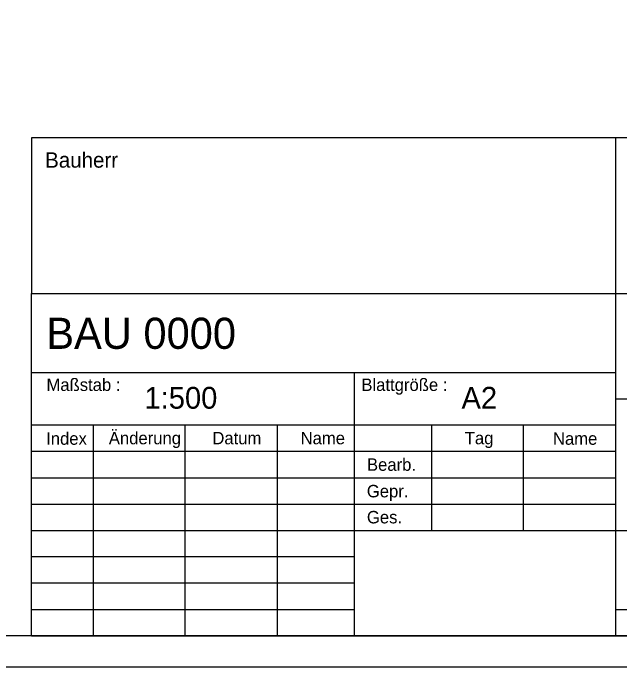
# Model space of a CAD drawing. Extents: x 0 to 297, y 0 to 210.
# Drawn here: x 204.1 to 252.8, y 0 to 52.5 of the extents above; entities that cross this region are included whole.
import ezdxf

# ---------------------------------------------------------------- set-up
doc = ezdxf.new("R2010")
doc.units = 0
doc.layers.add('90_Plankopf', color=7, linetype='Continuous')

msp = doc.modelspace()

# ---------------------------------------------------------------- linework, layer by layer
at = {"layer": '90_Plankopf'}
for p, q in [((294.5, 42.495), (205.56, 42.495)), ((205.56, 42.495), (205.56, 29.995)), ((252.501, 29.995), (252.501, 42.495)), ((205.56, 29.995), (294.5, 29.995)), ((205.56, 2.5), (205.56, 29.995)), ((205.56, 29.995), (294.5, 29.995)), ((252.501, 2.5), (252.501, 29.995)), ((205.56, 23.65), (252.501, 23.65)), ((231.501, 2.5), (231.501, 23.65)), ((252.501, 21.535), (294.5, 21.535)), ((205.56, 19.435), (252.501, 19.435)), ((210.501, 19.42), (210.501, 2.5)), ((217.913, 2.5), (217.913, 19.42)), ((225.325, 2.5), (225.325, 19.42)), ((237.677, 19.42), (237.677, 10.96)), ((245.089, 10.96), (245.089, 19.42)), ((205.56, 17.315), (252.501, 17.315)), ((205.56, 15.19), (252.501, 15.19)), ((205.56, 13.075), (252.501, 13.075)), ((205.56, 10.96), (252.501, 10.96)), ((205.56, 10.96), (252.501, 10.96)), ((231.501, 10.96), (252.501, 10.96)), ((252.501, 10.96), (294.5, 10.96)), ((231.501, 8.845), (205.56, 8.845)), ((231.501, 6.73), (205.56, 6.73)), ((205.56, 4.615), (231.501, 4.615)), ((252.501, 4.615), (294.5, 4.615)), ((294.5, 2.5), (205.56, 2.5)), ((205.56, 2.5), (231.501, 2.5)), ((211.4, 2.5), (294.5, 2.5)), ((211.4, 2.5), (294.5, 2.5))]:
    msp.add_line(p, q, dxfattribs=at)
for points in [[(0, 0), (297, 0), (297, 210), (0, 210)], [(12.5, 207.5), (294.5, 207.5), (294.5, 2.5), (12.5, 2.5)]]:
    msp.add_lwpolyline(points, close=True, dxfattribs=at)

# ---------------------------------------------------------------- texts
for s, height, p in [('Bauherr', 1.2318, (206.651, 40.087)), ('BAU 0000      ', 2.5, (206.745, 25.538)), ('Maßstab :', 1, (206.758, 22.158)), ('Blattgröße :', 0.99995, (232.058, 22.158)), ('1:500    ', 1.75, (214.631, 20.734)), ('A2       ', 1.75, (240.1, 20.734)), ('Änderung', 1, (211.767, 17.875)), ('Index', 1, (206.734, 17.837)), ('Datum', 1, (220.084, 17.875)), ('Name', 1, (227.174, 17.875)), ('Tag', 1, (240.362, 17.875)), ('Name', 1, (247.446, 17.837)), ('Bearb.', 1, (232.507, 15.745)), ('Gepr.', 1, (232.495, 13.615)), ('Ges.', 1, (232.502, 11.524))]:
    msp.add_text(s, height=height, dxfattribs=at).set_placement(p)

doc.saveas('drawing.dxf')
